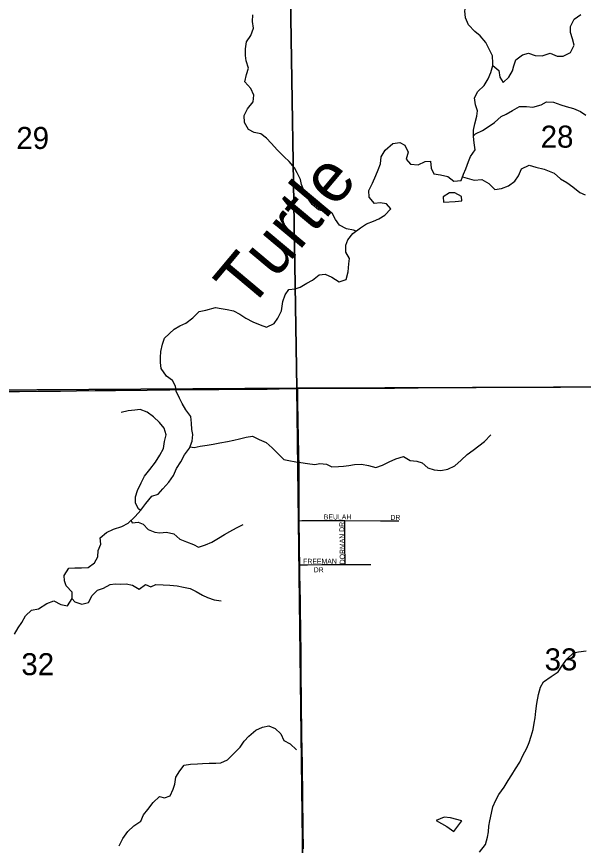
# Model space of a CAD drawing. Extents: x 0 to 1391, y -24 to 440.
# Drawn here: x 416.5 to 438.04, y 332.13 to 363.63 of the extents above; entities that cross this region are included whole.
import ezdxf

# ---------------------------------------------------------------- set-up
doc = ezdxf.new("R2010")
doc.units = 0
for name, color, linetype in [('GM_X_Minor_Lake', 7, 'Continuous'), ('GM_X_Minor_River', 7, 'Continuous'), ('GM_X_Minor_River_Text', 7, 'Continuous'), ('GM_X_Section', 7, 'Continuous'), ('GM_X_Section_Text', 7, 'Continuous'), ('GM_X_State_Route', 7, 'Continuous'), ('GM_X_Township_Road', 7, 'Continuous'), ('GM_X_Township_Subdivision', 7, 'Continuous'), ('GM_X_Township_Subdivision_Text', 7, 'Continuous')]:
    doc.layers.add(name, color=color, linetype=linetype)

msp = doc.modelspace()

# ---------------------------------------------------------------- linework, layer by layer
at = {"layer": 'GM_X_Minor_Lake'}
msp.add_line((433.417, 356.624), (433.405, 356.791), dxfattribs=at)
for points in [[(433.405, 356.791), (433.156, 356.933), (432.951, 356.929), (432.713, 356.783), (432.723, 356.58)], [(432.723, 356.58), (433.166, 356.599), (433.417, 356.624)], [(433.418, 333.063), (432.987, 333.18), (432.744, 333.2), (432.442, 333.078)], [(432.442, 333.078), (432.845, 332.85), (433.115, 332.655), (433.418, 333.063)]]:
    msp.add_lwpolyline(points, dxfattribs=at)
at = {"layer": 'GM_X_Minor_River'}
for points in [[(434.596, 361.761), (434.599, 361.854), (434.587, 362.134), (434.459, 362.386), (434.325, 362.646), (434.114, 362.891), (433.917, 363.06), (433.668, 363.32), (433.556, 363.58), (433.536, 363.845), (433.591, 364.095), (433.571, 364.368), (433.566, 364.641), (433.53, 364.869), (433.357, 365.122), (433.191, 365.313), (432.988, 365.566), (432.73, 365.736), (432.534, 365.943), (432.392, 366.202), (432.204, 366.455)], [(429.405, 355.476), (429.308, 355.512), (429.035, 355.564), (428.772, 355.698), (428.624, 355.913), (428.491, 356.158), (428.233, 356.209), (427.976, 356.29), (427.737, 356.485), (427.551, 356.739), (427.434, 356.999), (427.324, 357.251), (427.29, 357.441), (427.165, 357.694), (427.062, 357.885), (426.861, 358.117), (426.666, 358.295), (426.412, 358.551), (426.173, 358.813), (426.002, 359.006), (425.777, 359.178), (425.534, 359.221), (425.308, 359.339), (425.161, 359.607), (425.143, 359.873), (425.269, 360.121), (425.486, 360.389), (425.521, 360.646), (425.396, 360.898), (425.173, 361.153), (425.231, 361.432), (425.311, 361.673), (425.225, 361.948), (425.198, 362.146), (425.202, 362.403), (425.237, 362.675), (425.401, 362.914), (425.505, 363.193), (425.463, 363.444), (425.475, 363.694)], [(433.753, 358.315), (433.923, 358.563), (433.887, 358.829), (433.859, 359.072), (433.861, 359.307), (433.916, 359.549), (433.988, 359.844), (434.012, 360.041), (433.938, 360.276), (433.895, 360.535), (434.026, 360.776), (434.272, 361.008), (434.419, 361.264), (434.52, 361.506), (434.599, 361.77), (434.825, 361.578), (434.861, 361.327), (434.989, 361.121), (435.211, 361.331), (435.343, 361.565), (435.39, 361.761), (435.468, 361.988), (435.721, 362.174), (435.958, 362.232), (436.208, 362.146), (436.475, 362.135), (436.78, 362.238), (437.046, 362.129), (437.274, 362.126), (437.542, 362.267), (437.689, 362.539), (437.63, 362.782), (437.548, 363.026), (437.543, 363.253), (437.682, 363.525), (437.935, 363.704)], [(433.859, 359.095), (433.943, 359.169), (434.203, 359.303), (434.456, 359.467), (434.655, 359.609), (434.909, 359.833), (435.1, 359.922), (435.345, 360.063), (435.605, 360.212), (435.871, 360.209), (436.122, 360.183), (436.428, 360.278), (436.642, 360.389), (436.908, 360.379), (437.181, 360.269), (437.379, 360.207), (437.66, 360.135), (437.925, 360.018), (438.129, 359.879)], [(421.412, 345.127), (421.643, 345.397), (421.88, 345.478), (422.057, 345.68), (422.28, 345.935), (422.457, 346.191), (422.574, 346.447), (422.736, 346.71), (422.883, 346.974), (423.076, 347.222), (423.177, 347.486), (423.195, 347.743), (423.166, 347.933), (423.153, 348.176), (423.118, 348.434), (422.937, 348.678), (422.795, 348.923), (422.69, 349.128), (422.563, 349.388), (422.534, 349.585), (422.422, 349.791), (422.203, 349.968), (421.992, 350.251), (421.972, 350.478), (421.973, 350.668), (421.983, 350.895), (422.039, 351.182), (422.125, 351.401), (422.493, 351.753), (422.7, 351.879), (422.93, 351.975), (423.198, 352.177), (423.444, 352.416), (423.695, 352.466), (424.054, 352.568), (424.275, 352.535), (424.503, 352.502), (424.746, 352.439), (424.981, 352.315), (425.215, 352.161), (425.481, 352.029), (425.761, 351.912), (425.997, 351.825), (426.287, 351.966), (426.426, 352.169), (426.566, 352.44), (426.622, 352.796), (426.701, 353.053), (426.84, 353.256), (427.091, 353.283), (427.282, 353.341), (427.527, 353.498), (427.741, 353.617), (427.994, 353.818), (428.223, 353.838), (428.481, 353.722), (428.753, 353.552), (429.021, 353.639), (429.099, 353.927), (429.125, 354.229), (429.157, 354.434), (429.015, 354.678), (429.017, 354.936), (429.088, 355.14), (429.28, 355.38), (429.571, 355.604), (429.794, 355.753), (430.061, 355.856), (430.267, 355.944), (430.497, 356.086), (430.72, 356.326), (430.562, 356.517), (430.311, 356.55), (430.105, 356.53), (429.902, 356.767), (429.881, 357.025), (430.028, 357.297), (430.153, 357.591), (430.246, 357.802), (430.324, 358.036), (430.357, 358.294), (430.504, 358.557), (430.803, 358.804), (431.063, 358.839), (431.252, 358.746), (431.379, 358.479), (431.301, 358.214), (431.466, 358.015), (431.755, 357.997), (432.031, 358.123), (432.229, 358.128), (432.257, 357.87), (432.361, 357.656), (432.612, 357.615), (432.886, 357.552), (433.12, 357.375), (433.395, 357.402), (433.488, 357.643), (433.566, 357.839), (433.668, 358.119), (433.753, 358.315)], [(433.45, 357.544), (433.624, 357.482), (433.882, 357.411), (434.179, 357.438), (434.444, 357.291), (434.678, 357.061), (434.922, 357.096), (435.189, 357.199), (435.435, 357.378), (435.574, 357.573), (435.69, 357.845), (435.981, 357.978), (436.231, 357.907), (436.543, 357.828), (436.732, 357.757), (436.922, 357.672), (437.164, 357.457), (437.406, 357.325), (437.641, 357.163), (437.905, 356.948), (438.11, 356.854)], [(421.214, 344.857), (421.136, 344.918), (421.016, 345.132), (421.018, 345.374), (421.097, 345.616), (421.229, 345.91), (421.361, 346.158), (421.561, 346.414), (421.777, 346.691), (421.939, 346.955), (422.086, 347.218), (422.127, 347.483), (422.182, 347.732), (422.109, 347.991), (421.935, 348.205), (421.709, 348.42), (421.459, 348.597), (421.194, 348.699), (420.996, 348.671), (420.736, 348.644), (420.477, 348.579)], [(423.098, 347.278), (423.251, 347.25), (423.48, 347.3), (423.747, 347.335), (423.976, 347.378), (424.228, 347.428), (424.517, 347.485), (424.754, 347.528), (424.968, 347.578), (425.219, 347.643), (425.471, 347.678), (425.721, 347.554), (425.979, 347.437), (426.213, 347.238), (426.439, 347.008), (426.658, 346.793), (426.848, 346.76), (427.107, 346.704), (427.304, 346.687), (427.555, 346.638), (427.829, 346.605), (428.02, 346.648), (428.278, 346.622), (428.483, 346.514), (428.727, 346.534), (428.925, 346.546), (429.123, 346.567), (429.337, 346.61), (429.611, 346.622), (429.877, 346.565), (430.15, 346.486), (430.402, 346.574), (430.655, 346.708), (430.907, 346.826), (431.197, 346.914), (431.455, 346.759), (431.706, 346.726), (431.911, 346.67), (432.13, 346.478), (432.365, 346.407), (432.624, 346.374), (432.891, 346.432), (433.151, 346.55), (433.396, 346.767), (433.619, 346.984), (433.849, 347.155), (434.071, 347.32), (434.286, 347.476), (434.524, 347.731)], [(416.424, 340.162), (416.556, 340.403), (416.702, 340.599), (416.842, 340.847), (417.072, 341.072), (417.339, 341.121), (417.653, 341.322), (417.921, 341.425), (418.186, 341.286), (418.437, 341.23), (418.614, 341.508), (418.616, 341.75), (418.383, 341.988), (418.324, 342.178), (418.303, 342.383), (418.488, 342.661), (418.709, 342.681), (418.968, 342.678), (419.219, 342.69), (419.464, 342.862), (419.588, 343.095), (419.598, 343.33), (419.699, 343.571), (419.679, 343.814), (419.917, 344.016), (420.184, 344.141), (420.505, 344.251), (420.742, 344.37), (421.011, 344.624), (421.227, 344.872), (421.412, 345.127)], [(420.86, 344.481), (420.895, 344.391), (421.124, 344.418), (421.313, 344.34), (421.502, 344.133), (421.752, 344.039), (421.942, 344.007), (422.201, 344.034), (422.475, 343.97), (422.701, 343.763), (422.952, 343.661), (423.225, 343.56), (423.414, 343.466), (423.674, 343.547), (423.918, 343.65), (424.179, 343.806), (424.401, 343.94), (424.6, 344.059), (424.852, 344.2), (425.105, 344.326)], [(418.61, 341.5), (418.72, 341.385), (418.978, 341.291), (419.23, 341.364), (419.369, 341.628), (419.577, 341.83), (419.806, 341.903), (420.058, 342.044), (420.249, 342.064), (420.447, 342.062), (420.66, 342.067), (420.911, 342.019), (421.153, 341.872), (421.398, 342.043), (421.603, 341.957), (421.794, 342.046), (422.076, 342.027), (422.327, 342.024), (422.601, 341.998), (422.837, 341.943), (423.095, 341.887), (423.33, 341.778), (423.565, 341.638), (423.754, 341.553), (424.012, 341.466), (424.271, 341.418)], [(434.09, 331.865), (434.316, 332.157), (434.389, 332.444), (434.43, 332.64), (434.442, 332.86), (434.483, 333.057), (434.541, 333.359), (434.599, 333.593), (434.717, 333.849), (434.827, 334.067), (435.022, 334.345), (435.179, 334.6), (435.319, 334.81), (435.453, 335.035), (435.624, 335.29), (435.743, 335.539), (435.892, 335.824), (435.972, 336.043), (436.06, 336.277), (436.125, 336.533), (436.167, 336.776), (436.201, 336.98), (436.236, 337.23), (436.271, 337.525), (436.337, 337.858), (436.411, 338.145), (436.521, 338.348), (436.813, 338.547), (437.075, 338.725), (437.223, 338.942), (437.411, 339.205), (437.666, 339.443), (437.857, 339.485), (438.139, 339.526)], [(420.401, 332.113), (420.539, 332.385), (420.723, 332.656), (420.96, 332.874), (421.226, 333.053), (421.327, 333.287), (421.487, 333.49), (421.686, 333.762), (421.93, 333.987), (422.12, 333.94), (422.333, 334.014), (422.456, 334.263), (422.517, 334.459), (422.557, 334.724), (422.71, 334.958), (422.871, 335.176), (423.106, 335.212), (423.372, 335.233), (423.57, 335.246), (423.813, 335.259), (424.071, 335.257), (424.261, 335.27), (424.519, 335.374), (424.756, 335.622), (425, 335.863), (425.146, 336.089), (425.322, 336.284), (425.596, 336.509), (425.847, 336.621), (426.091, 336.672), (426.325, 336.571), (426.537, 336.365), (426.657, 336.114), (426.892, 335.99), (427.133, 335.761)]]:
    msp.add_lwpolyline(points, dxfattribs=at)
at = {"layer": 'GM_X_Section'}
for points in [[(426.829, 369.053), (427.145, 349.502), (407.364, 349.38), (407.286, 369.115)], [(447.056, 369.114), (447.184, 349.582), (427.145, 349.502), (426.829, 369.053)], [(427.145, 349.502), (427.403, 329.248), (407.447, 329.121), (407.364, 349.38)], [(447.184, 349.582), (447.102, 329.433), (427.403, 329.248), (427.145, 349.502)]]:
    msp.add_lwpolyline(points, close=True, dxfattribs=at)
at = {"layer": 'GM_X_State_Route'}
for points in [[(409.891, 349.308), (410.025, 349.316), (410.398, 349.327), (411.405, 349.34), (412.1, 349.349), (412.474, 349.349), (412.847, 349.347), (414.421, 349.363), (415.179, 349.375), (415.689, 349.38), (416.099, 349.383), (416.549, 349.381)], [(416.549, 349.381), (416.608, 349.381), (417.304, 349.387), (418.174, 349.395), (418.783, 349.402), (419.491, 349.413), (420.261, 349.421), (421.466, 349.427), (422.324, 349.443), (422.92, 349.449), (423.641, 349.452), (424.188, 349.458)], [(424.188, 349.458), (425.268, 349.468), (426.026, 349.474), (426.933, 349.488), (427.188, 349.49), (429.43, 349.501), (430.86, 349.512), (431.754, 349.521), (432.587, 349.529), (433.395, 349.529), (433.966, 349.534), (434.55, 349.542), (435.134, 349.541), (436.104, 349.546), (436.899, 349.553), (437.247, 349.557), (439.434, 349.563), (440.167, 349.561), (440.726, 349.564), (442.006, 349.57), (442.951, 349.572), (443.92, 349.576), (444.118, 349.577)]]:
    msp.add_lwpolyline(points, dxfattribs=at)
at = {"layer": 'GM_X_Township_Road'}
for points in [[(427.24, 344.47), (427.238, 344.657), (427.241, 345.215), (427.24, 345.539), (427.238, 345.874), (427.235, 346.258), (427.232, 346.556), (427.227, 346.966), (427.224, 347.177), (427.217, 347.487), (427.209, 347.86), (427.204, 348.034), (427.2, 348.245), (427.197, 348.468), (427.191, 348.791), (427.188, 349.49)], [(427.259, 342.789), (427.259, 342.842), (427.254, 343.34), (427.247, 343.799), (427.242, 344.234), (427.24, 344.47)], [(427.404, 331.997), (427.401, 332.245), (427.396, 332.506), (427.389, 332.991), (427.38, 333.748), (427.376, 334.283), (427.367, 334.892), (427.361, 335.277), (427.353, 335.712), (427.343, 336.357), (427.335, 336.767), (427.331, 337.128), (427.325, 337.587), (427.321, 337.898), (427.314, 338.37), (427.308, 338.917), (427.308, 339.588), (427.306, 340.122), (427.304, 340.333), (427.286, 341.078), (427.287, 341.488), (427.278, 341.836), (427.261, 342.507), (427.259, 342.789)]]:
    msp.add_lwpolyline(points, dxfattribs=at)
at = {"layer": 'GM_X_Township_Subdivision'}
for points in [[(427.24, 344.47), (427.343, 344.471), (428.972, 344.475)], [(428.972, 344.475), (430.328, 344.465), (430.701, 344.466), (431.025, 344.469)], [(428.983, 342.803), (428.974, 343.617), (428.974, 343.703), (428.975, 343.815), (428.976, 343.989), (428.973, 344.379), (428.972, 344.475)], [(427.259, 342.789), (427.384, 342.789), (427.558, 342.79), (428.103, 342.802), (428.438, 342.801), (428.955, 342.803), (428.983, 342.803)], [(428.983, 342.803), (429.961, 342.802)]]:
    msp.add_lwpolyline(points, dxfattribs=at)

# ---------------------------------------------------------------- texts
at = {"layer": 'GM_X_Minor_River_Text'}
msp.add_text('Turtle', height=1.8941, rotation=50.0451, dxfattribs=at).set_placement((425.338, 352.442))
at = {"layer": 'GM_X_Section_Text'}
for s, p in [('29', (416.49, 358.597)), ('28', (436.415, 358.647)), ('33', (436.565, 338.78)), ('32', (416.682, 338.597))]:
    msp.add_text(s, height=0.8371, rotation=0, dxfattribs=at).set_placement(p)
at = {"layer": 'GM_X_Township_Subdivision_Text'}
for s, rotation, p in [('BEULAH', 0, (428.174, 344.515)), ('DR', 0, (430.707, 344.498)), ('DORMAN DR', 90.6737, (428.971, 342.812)), ('FREEMAN', 0, (427.39, 342.831)), ('DR', 0, (427.79, 342.509))]:
    msp.add_text(s, height=0.1894, rotation=rotation, dxfattribs=at).set_placement(p)

doc.saveas('drawing.dxf')
